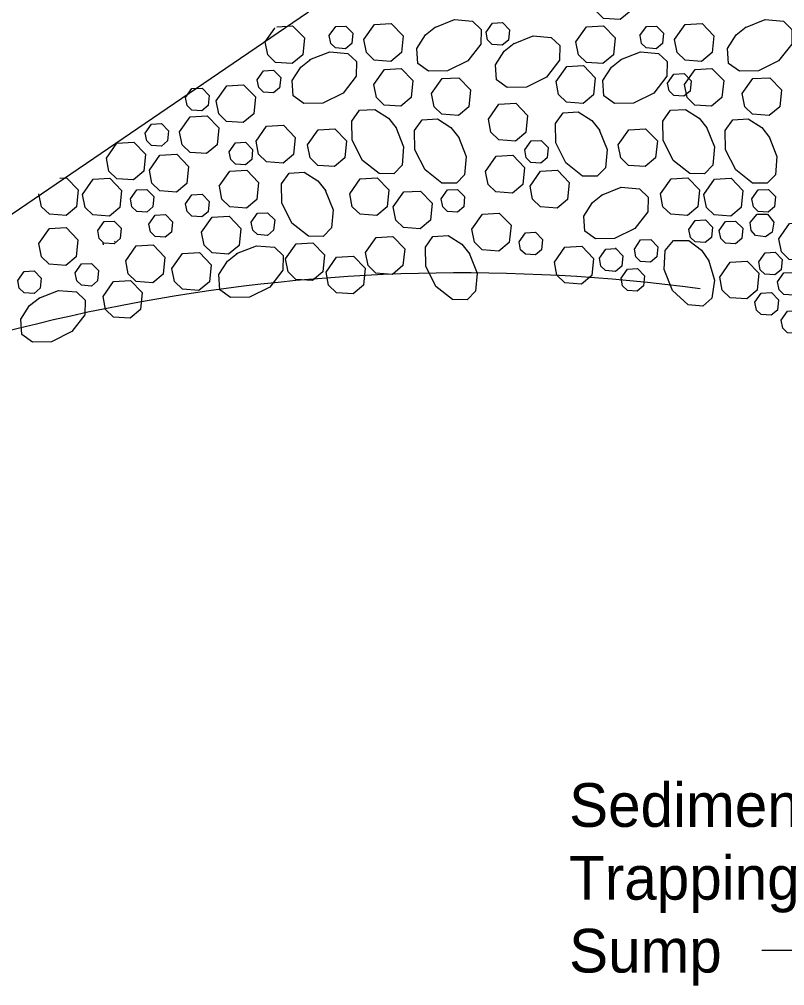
# Model space of a CAD drawing. Extents: x 6707406 to 6714471, y 1868570 to 1872341.
# Drawn here: x 6709570.8 to 6709696.9, y 1870139.3 to 1870298.5 of the extents above; entities that cross this region are included whole.
import ezdxf

# ---------------------------------------------------------------- set-up
doc = ezdxf.new("R2010")
doc.units = 0
for name, color, linetype in [('56 Stg 3 Anno', 7, 'Continuous'), ('57 Undefined', 7, 'Continuous'), ('60 Nongeo Data', 7, 'Continuous')]:
    doc.layers.add(name, color=color, linetype=linetype)

msp = doc.modelspace()

# ---------------------------------------------------------------- linework, layer by layer
at = {"layer": '56 Stg 3 Anno'}
msp.add_line((6709713.58, 1870145.05), (6709693.08, 1870145.05), dxfattribs=at)
at = {"layer": '60 Nongeo Data'}
msp.add_line((6709495.94, 1870216.26), (6709884.38, 1870481.01), dxfattribs=at)
for points in [[(6709665.33, 1870302.03), (6709667.07, 1870304.51), (6709669.85, 1870304.67), (6709671.78, 1870302.66), (6709671.5, 1870299.86), (6709669.79, 1870298.43), (6709667.04, 1870298.63), (6709665.75, 1870299.88), (6709665.34, 1870302.03)], [(6709639.21, 1870297.14), (6709642.47, 1870298.43), (6709645.46, 1870298.17), (6709646.88, 1870296.82), (6709646.83, 1870294.4), (6709644.68, 1870291.64), (6709641.34, 1870289.97), (6709638.2, 1870289.92), (6709636.44, 1870291.18), (6709636.27, 1870293.68), (6709637.7, 1870295.91), (6709639.35, 1870297.23)], [(6709690.41, 1870297.14), (6709693.66, 1870298.43), (6709696.65, 1870298.17), (6709698.07, 1870296.82), (6709698.03, 1870294.4), (6709695.87, 1870291.64), (6709692.54, 1870289.97), (6709689.4, 1870289.92), (6709687.63, 1870291.18), (6709687.46, 1870293.68), (6709688.9, 1870295.91), (6709690.54, 1870297.23)], [(6709613.19, 1870297.27), (6709615.8, 1870297.42), (6709617.74, 1870295.42), (6709617.46, 1870292.61), (6709615.74, 1870291.19), (6709613, 1870291.39), (6709611.71, 1870292.64), (6709611.29, 1870294.79)], [(6709611.29, 1870294.79), (6709612.88, 1870297.05)], [(6709612.88, 1870297.05), (6709612.88, 1870297.06)], [(6709621.84, 1870295.8), (6709622.89, 1870297.29), (6709624.55, 1870297.38), (6709625.71, 1870296.18), (6709625.54, 1870294.5), (6709624.51, 1870293.64), (6709622.87, 1870293.76), (6709622.09, 1870294.51), (6709621.84, 1870295.8)], [(6709627.54, 1870295.16), (6709629.28, 1870297.64), (6709632.06, 1870297.8), (6709633.99, 1870295.79), (6709633.71, 1870292.99), (6709631.99, 1870291.56), (6709629.25, 1870291.76), (6709627.96, 1870293.01), (6709627.54, 1870295.16)], [(6709647.67, 1870296.38), (6709648.71, 1870297.86), (6709650.38, 1870297.95), (6709651.54, 1870296.75), (6709651.37, 1870295.07), (6709650.34, 1870294.22), (6709648.7, 1870294.33), (6709647.92, 1870295.09), (6709647.67, 1870296.38)], [(6709662.48, 1870294.79), (6709664.22, 1870297.26), (6709667, 1870297.42), (6709668.93, 1870295.42), (6709668.65, 1870292.61), (6709666.93, 1870291.19), (6709664.19, 1870291.39), (6709662.9, 1870292.64), (6709662.48, 1870294.79)], [(6709673.03, 1870295.8), (6709674.08, 1870297.29), (6709675.74, 1870297.38), (6709676.9, 1870296.18), (6709676.74, 1870294.5), (6709675.71, 1870293.64), (6709674.06, 1870293.76), (6709673.29, 1870294.51), (6709673.04, 1870295.8)], [(6709678.74, 1870295.16), (6709680.47, 1870297.64), (6709683.25, 1870297.8), (6709685.18, 1870295.79), (6709684.9, 1870292.99), (6709683.19, 1870291.56), (6709680.45, 1870291.76), (6709679.15, 1870293.01), (6709678.74, 1870295.16)], [(6709652.18, 1870294.47), (6709655.43, 1870295.76), (6709658.42, 1870295.5), (6709659.84, 1870294.15), (6709659.79, 1870291.73), (6709657.64, 1870288.97), (6709654.31, 1870287.3), (6709651.17, 1870287.25), (6709649.4, 1870288.51), (6709649.23, 1870291.01), (6709650.67, 1870293.24), (6709652.31, 1870294.55)], [(6709618.66, 1870291.84), (6709621.91, 1870293.13), (6709624.9, 1870292.87), (6709626.32, 1870291.52), (6709626.28, 1870289.1), (6709624.12, 1870286.34), (6709620.79, 1870284.67), (6709617.65, 1870284.62), (6709615.88, 1870285.87), (6709615.71, 1870288.38), (6709617.15, 1870290.61), (6709618.79, 1870291.92)], [(6709669.85, 1870291.84), (6709673.11, 1870293.13), (6709676.1, 1870292.87), (6709677.52, 1870291.52), (6709677.47, 1870289.1), (6709675.32, 1870286.34), (6709671.98, 1870284.67), (6709668.84, 1870284.62), (6709667.08, 1870285.87), (6709666.91, 1870288.38), (6709668.34, 1870290.61), (6709669.99, 1870291.92)], [(6709629.18, 1870287.76), (6709630.92, 1870290.23), (6709633.69, 1870290.39), (6709635.62, 1870288.39), (6709635.35, 1870285.58), (6709633.63, 1870284.16), (6709630.89, 1870284.35), (6709629.6, 1870285.61), (6709629.18, 1870287.76)], [(6709659.21, 1870288.24), (6709660.95, 1870290.72), (6709663.73, 1870290.88), (6709665.66, 1870288.87), (6709665.38, 1870286.07), (6709663.66, 1870284.64), (6709660.92, 1870284.84), (6709659.63, 1870286.09), (6709659.21, 1870288.24)], [(6709680.37, 1870287.76), (6709682.11, 1870290.23), (6709684.89, 1870290.39), (6709686.82, 1870288.39), (6709686.54, 1870285.58), (6709684.82, 1870284.16), (6709682.08, 1870284.35), (6709680.79, 1870285.61), (6709680.37, 1870287.76)], [(6709609.96, 1870288.52), (6709611.01, 1870290.01), (6709612.67, 1870290.1), (6709613.83, 1870288.9), (6709613.66, 1870287.22), (6709612.63, 1870286.36), (6709610.99, 1870286.48), (6709610.21, 1870287.23), (6709609.96, 1870288.52)], [(6709638.69, 1870286.24), (6709640.43, 1870288.72), (6709643.2, 1870288.87), (6709645.13, 1870286.87), (6709644.85, 1870284.07), (6709643.14, 1870282.64), (6709640.4, 1870282.84), (6709639.11, 1870284.09), (6709638.69, 1870286.24)], [(6709677.58, 1870287.97), (6709678.62, 1870289.45), (6709680.29, 1870289.55), (6709681.45, 1870288.35), (6709681.28, 1870286.66), (6709680.25, 1870285.81), (6709678.61, 1870285.93), (6709677.83, 1870286.68), (6709677.58, 1870287.97)], [(6709689.88, 1870286.24), (6709691.62, 1870288.72), (6709694.4, 1870288.87), (6709696.33, 1870286.87), (6709696.05, 1870284.07), (6709694.33, 1870282.64), (6709691.59, 1870282.84), (6709690.3, 1870284.09), (6709689.88, 1870286.24)], [(6709598.16, 1870285.58), (6709599.2, 1870287.06), (6709600.87, 1870287.16), (6709602.03, 1870285.96), (6709601.86, 1870284.27), (6709600.83, 1870283.42), (6709599.18, 1870283.54), (6709598.41, 1870284.29), (6709598.16, 1870285.58)], [(6709603.21, 1870285.07), (6709604.95, 1870287.54), (6709607.73, 1870287.7), (6709609.66, 1870285.7), (6709609.38, 1870282.89), (6709607.67, 1870281.47), (6709604.92, 1870281.67), (6709603.63, 1870282.92), (6709603.22, 1870285.07)], [(6709648.05, 1870282.03), (6709649.79, 1870284.51), (6709652.57, 1870284.67), (6709654.5, 1870282.66), (6709654.22, 1870279.86), (6709652.51, 1870278.43), (6709649.77, 1870278.63), (6709648.48, 1870279.88), (6709648.06, 1870282.03)], [(6709597.18, 1870279.97), (6709598.92, 1870282.44), (6709601.7, 1870282.6), (6709603.63, 1870280.6), (6709603.35, 1870277.79), (6709601.63, 1870276.37), (6709598.89, 1870276.57), (6709597.6, 1870277.82), (6709597.18, 1870279.97)], [(6709632.8, 1870280.71), (6709634.09, 1870277.45), (6709633.83, 1870274.46), (6709632.48, 1870273.04), (6709630.05, 1870273.09), (6709627.3, 1870275.25), (6709625.63, 1870278.58), (6709625.58, 1870281.72), (6709626.83, 1870283.49), (6709629.33, 1870283.65), (6709631.57, 1870282.22), (6709632.88, 1870280.58)], [(6709666.31, 1870280.29), (6709667.6, 1870277.03), (6709667.35, 1870274.04), (6709666, 1870272.62), (6709663.57, 1870272.67), (6709660.81, 1870274.82), (6709659.15, 1870278.16), (6709659.09, 1870281.3), (6709660.35, 1870283.06), (6709662.85, 1870283.23), (6709665.09, 1870281.8), (6709666.4, 1870280.15)], [(6709683.99, 1870280.71), (6709685.28, 1870277.45), (6709685.02, 1870274.46), (6709683.67, 1870273.04), (6709681.25, 1870273.09), (6709678.49, 1870275.25), (6709676.83, 1870278.58), (6709676.77, 1870281.72), (6709678.03, 1870283.49), (6709680.53, 1870283.65), (6709682.76, 1870282.22), (6709684.07, 1870280.58)], [(6709591.5, 1870279.75), (6709592.54, 1870281.23), (6709594.21, 1870281.33), (6709595.37, 1870280.13), (6709595.2, 1870278.44), (6709594.17, 1870277.59), (6709592.53, 1870277.71), (6709591.75, 1870278.46), (6709591.5, 1870279.75)], [(6709609.77, 1870278.41), (6709611.51, 1870280.88), (6709614.29, 1870281.04), (6709616.22, 1870279.04), (6709615.94, 1870276.23), (6709614.22, 1870274.8), (6709611.48, 1870275), (6709610.19, 1870276.25), (6709609.77, 1870278.4)], [(6709643.11, 1870279.13), (6709644.4, 1870275.88), (6709644.14, 1870272.89), (6709642.79, 1870271.47), (6709640.37, 1870271.51), (6709637.61, 1870273.67), (6709635.94, 1870277), (6709635.89, 1870280.14), (6709637.14, 1870281.91), (6709639.65, 1870282.07), (6709641.88, 1870280.64), (6709643.19, 1870279)], [(6709694.3, 1870279.13), (6709695.59, 1870275.88), (6709695.34, 1870272.89), (6709693.98, 1870271.47), (6709691.56, 1870271.51), (6709688.8, 1870273.67), (6709687.14, 1870277), (6709687.08, 1870280.14), (6709688.34, 1870281.91), (6709690.84, 1870282.07), (6709693.08, 1870280.64), (6709694.39, 1870279)], [(6709618.24, 1870277.83), (6709619.98, 1870280.3), (6709622.76, 1870280.46), (6709624.69, 1870278.46), (6709624.41, 1870275.65), (6709622.7, 1870274.23), (6709619.96, 1870274.42), (6709618.67, 1870275.67), (6709618.25, 1870277.83)], [(6709669.44, 1870277.83), (6709671.18, 1870280.3), (6709673.95, 1870280.46), (6709675.89, 1870278.46), (6709675.61, 1870275.65), (6709673.89, 1870274.23), (6709671.15, 1870274.42), (6709669.86, 1870275.67), (6709669.44, 1870277.83)], [(6709585.11, 1870275.63), (6709586.85, 1870278.1), (6709589.62, 1870278.26), (6709591.56, 1870276.26), (6709591.28, 1870273.45), (6709589.56, 1870272.03), (6709586.82, 1870272.23), (6709585.53, 1870273.48), (6709585.11, 1870275.63)], [(6709605.35, 1870276.68), (6709606.39, 1870278.16), (6709608.06, 1870278.26), (6709609.21, 1870277.06), (6709609.05, 1870275.37), (6709608.02, 1870274.52), (6709606.37, 1870274.64), (6709605.6, 1870275.39), (6709605.35, 1870276.68)], [(6709654.03, 1870276.96), (6709655.08, 1870278.45), (6709656.74, 1870278.54), (6709657.9, 1870277.34), (6709657.73, 1870275.66), (6709656.7, 1870274.8), (6709655.06, 1870274.92), (6709654.28, 1870275.67), (6709654.03, 1870276.96)], [(6709592.19, 1870273.62), (6709593.93, 1870276.09), (6709596.7, 1870276.25), (6709598.63, 1870274.25), (6709598.35, 1870271.44), (6709596.64, 1870270.02), (6709593.9, 1870270.22), (6709592.61, 1870271.47), (6709592.19, 1870273.62)], [(6709647.57, 1870273.44), (6709649.31, 1870275.92), (6709652.08, 1870276.08), (6709654.01, 1870274.07), (6709653.74, 1870271.27), (6709652.02, 1870269.84), (6709649.28, 1870270.04), (6709647.99, 1870271.29), (6709647.57, 1870273.44)], [(6709603.72, 1870270.99), (6709605.46, 1870273.46), (6709608.24, 1870273.62), (6709610.17, 1870271.62), (6709609.89, 1870268.81), (6709608.18, 1870267.38), (6709605.43, 1870267.58), (6709604.14, 1870268.83), (6709603.73, 1870270.98)], [(6709621.17, 1870270.36), (6709622.46, 1870267.11), (6709622.2, 1870264.12), (6709620.85, 1870262.7), (6709618.43, 1870262.74), (6709615.67, 1870264.9), (6709614.01, 1870268.23), (6709613.95, 1870271.37), (6709615.21, 1870273.14), (6709617.71, 1870273.31), (6709619.94, 1870271.87), (6709621.25, 1870270.23)], [(6709654.92, 1870270.99), (6709656.66, 1870273.46), (6709659.43, 1870273.62), (6709661.37, 1870271.62), (6709661.09, 1870268.81), (6709659.37, 1870267.38), (6709656.63, 1870267.58), (6709655.34, 1870268.83), (6709654.92, 1870270.98)], [(6709577.42, 1870272.33), (6709578.53, 1870272.39), (6709580.46, 1870270.39), (6709580.18, 1870267.59), (6709578.46, 1870266.16), (6709575.72, 1870266.36), (6709574.43, 1870267.61), (6709574.01, 1870269.76)], [(6709581.17, 1870269.65), (6709582.91, 1870272.13), (6709585.68, 1870272.29), (6709587.62, 1870270.28), (6709587.34, 1870267.48), (6709585.62, 1870266.05), (6709582.88, 1870266.25), (6709581.59, 1870267.5), (6709581.17, 1870269.65)], [(6709625.21, 1870269.76), (6709626.94, 1870272.23), (6709629.72, 1870272.39), (6709631.65, 1870270.39), (6709631.37, 1870267.59), (6709629.66, 1870266.16), (6709626.92, 1870266.36), (6709625.63, 1870267.61), (6709625.21, 1870269.76)], [(6709676.4, 1870269.76), (6709678.14, 1870272.23), (6709680.92, 1870272.39), (6709682.85, 1870270.39), (6709682.57, 1870267.59), (6709680.85, 1870266.16), (6709678.11, 1870266.36), (6709676.82, 1870267.61), (6709676.4, 1870269.76)], [(6709683.55, 1870269.65), (6709685.29, 1870272.13), (6709688.07, 1870272.29), (6709690, 1870270.28), (6709689.72, 1870267.48), (6709688.01, 1870266.05), (6709685.26, 1870266.25), (6709683.97, 1870267.5), (6709683.56, 1870269.65)], [(6709589.08, 1870268.89), (6709590.12, 1870270.37), (6709591.79, 1870270.47), (6709592.95, 1870269.27), (6709592.78, 1870267.59), (6709591.75, 1870266.73), (6709590.11, 1870266.85), (6709589.33, 1870267.6), (6709589.08, 1870268.89)], [(6709598.16, 1870268.09), (6709599.2, 1870269.57), (6709600.87, 1870269.67), (6709602.03, 1870268.47), (6709601.86, 1870266.79), (6709600.83, 1870265.93), (6709599.18, 1870266.05), (6709598.41, 1870266.8), (6709598.16, 1870268.09)], [(6709632.36, 1870267.57), (6709634.1, 1870270.04), (6709636.88, 1870270.2), (6709638.81, 1870268.2), (6709638.53, 1870265.4), (6709636.81, 1870263.97), (6709634.07, 1870264.17), (6709632.78, 1870265.42), (6709632.36, 1870267.57)], [(6709640.28, 1870268.89), (6709641.32, 1870270.37), (6709642.99, 1870270.47), (6709644.14, 1870269.27), (6709643.98, 1870267.59), (6709642.95, 1870266.73), (6709641.3, 1870266.85), (6709640.53, 1870267.6), (6709640.28, 1870268.89)], [(6709666.7, 1870269.53), (6709669.95, 1870270.82), (6709672.94, 1870270.56), (6709674.36, 1870269.21), (6709674.32, 1870266.79), (6709672.16, 1870264.03), (6709668.83, 1870262.37), (6709665.69, 1870262.31), (6709663.92, 1870263.57), (6709663.75, 1870266.07), (6709665.19, 1870268.31), (6709666.83, 1870269.62)], [(6709691.47, 1870268.89), (6709692.51, 1870270.37), (6709694.18, 1870270.47), (6709695.34, 1870269.27), (6709695.17, 1870267.59), (6709694.14, 1870266.73), (6709692.49, 1870266.85), (6709691.72, 1870267.6), (6709691.47, 1870268.89)], [(6709608.97, 1870265.05), (6709610.02, 1870266.54), (6709611.68, 1870266.63), (6709612.84, 1870265.43), (6709612.67, 1870263.75), (6709611.64, 1870262.89), (6709610, 1870263.01), (6709609.22, 1870263.76), (6709608.97, 1870265.05)], [(6709645.33, 1870263.91), (6709647.07, 1870266.39), (6709649.85, 1870266.55), (6709651.78, 1870264.55), (6709651.5, 1870261.74), (6709649.78, 1870260.31), (6709647.04, 1870260.51), (6709645.75, 1870261.76), (6709645.33, 1870263.91)], [(6709583.7, 1870263.67), (6709584.74, 1870265.15), (6709586.41, 1870265.25), (6709587.57, 1870264.05), (6709587.4, 1870262.37), (6709586.37, 1870261.51), (6709584.72, 1870261.63), (6709583.95, 1870262.38), (6709583.7, 1870263.67)], [(6709592.13, 1870264.75), (6709593.17, 1870266.23), (6709594.84, 1870266.33), (6709595.99, 1870265.13), (6709595.83, 1870263.44), (6709594.8, 1870262.59), (6709593.15, 1870262.71), (6709592.38, 1870263.46), (6709592.13, 1870264.75)], [(6709600.81, 1870263.41), (6709602.55, 1870265.88), (6709605.32, 1870266.04), (6709607.26, 1870264.04), (6709606.98, 1870261.23), (6709605.26, 1870259.81), (6709602.52, 1870260.01), (6709601.23, 1870261.26), (6709600.81, 1870263.41)], [(6709681.09, 1870263.85), (6709682.13, 1870265.33), (6709683.8, 1870265.43), (6709684.96, 1870264.23), (6709684.79, 1870262.55), (6709683.76, 1870261.69), (6709682.11, 1870261.81), (6709681.34, 1870262.56), (6709681.09, 1870263.85)], [(6709686.08, 1870263.67), (6709687.13, 1870265.15), (6709688.79, 1870265.25), (6709689.95, 1870264.05), (6709689.79, 1870262.37), (6709688.76, 1870261.51), (6709687.11, 1870261.63), (6709686.34, 1870262.38), (6709686.09, 1870263.67)], [(6709691.2, 1870264.99), (6709692.36, 1870266.39), (6709694.03, 1870266.36), (6709695.09, 1870265.07), (6709694.79, 1870263.4), (6709693.7, 1870262.63), (6709692.07, 1870262.88), (6709691.35, 1870263.68), (6709691.2, 1870264.99)], [(6709695.9, 1870262.34), (6709697.64, 1870264.82), (6709700.41, 1870264.98), (6709702.34, 1870262.98), (6709702.06, 1870260.17), (6709700.35, 1870258.74), (6709697.61, 1870258.94), (6709696.32, 1870260.19), (6709695.9, 1870262.34)], [(6709573.98, 1870261.53), (6709575.72, 1870264), (6709578.49, 1870264.16), (6709580.42, 1870262.16), (6709580.14, 1870259.35), (6709578.43, 1870257.93), (6709575.69, 1870258.13), (6709574.4, 1870259.38), (6709573.98, 1870261.53)], [(6709653.12, 1870261.82), (6709654.16, 1870263.31), (6709655.83, 1870263.4), (6709656.99, 1870262.2), (6709656.82, 1870260.52), (6709655.79, 1870259.66), (6709654.14, 1870259.78), (6709653.37, 1870260.53), (6709653.12, 1870261.82)], [(6709586.44, 1870261.83), (6709586.57, 1870261.94)], [(6709627.81, 1870260.07), (6709629.55, 1870262.54), (6709632.33, 1870262.7), (6709634.26, 1870260.7), (6709633.98, 1870257.9), (6709632.26, 1870256.47), (6709629.52, 1870256.67), (6709628.23, 1870257.92), (6709627.81, 1870260.07)], [(6709644.89, 1870259.94), (6709646.18, 1870256.69), (6709645.92, 1870253.7), (6709644.57, 1870252.28), (6709642.14, 1870252.33), (6709639.39, 1870254.48), (6709637.72, 1870257.81), (6709637.67, 1870260.95), (6709638.92, 1870262.72), (6709641.42, 1870262.89), (6709643.66, 1870261.46), (6709644.97, 1870259.81)], [(6709672.1, 1870260.64), (6709673.14, 1870262.13), (6709674.81, 1870262.22), (6709675.97, 1870261.02), (6709675.8, 1870259.34), (6709674.77, 1870258.48), (6709673.13, 1870258.6), (6709672.35, 1870259.35), (6709672.1, 1870260.64)], [(6709684.3, 1870258.84), (6709685.33, 1870255.5), (6709684.84, 1870252.54), (6709683.39, 1870251.22), (6709680.97, 1870251.46), (6709678.39, 1870253.82), (6709676.99, 1870257.27), (6709677.18, 1870260.41), (6709678.57, 1870262.07), (6709681.07, 1870262.05), (6709683.19, 1870260.44), (6709684.37, 1870258.7)], [(6709584.66, 1870261.33), (6709584.61, 1870261.59)], [(6709588.3, 1870258.69), (6709590.04, 1870261.17), (6709592.82, 1870261.33), (6709594.75, 1870259.32), (6709594.47, 1870256.52), (6709592.75, 1870255.09), (6709590.01, 1870255.29), (6709588.72, 1870256.54), (6709588.3, 1870258.69)], [(6709606.56, 1870259.89), (6709609.82, 1870261.18), (6709612.81, 1870260.92), (6709614.23, 1870259.57), (6709614.18, 1870257.14), (6709612.03, 1870254.38), (6709608.69, 1870252.72), (6709605.55, 1870252.66), (6709603.79, 1870253.92), (6709603.62, 1870256.42), (6709605.05, 1870258.66), (6709606.7, 1870259.97)], [(6709614.63, 1870259.04), (6709616.36, 1870261.51), (6709619.14, 1870261.67), (6709621.07, 1870259.67), (6709620.79, 1870256.87), (6709619.08, 1870255.44), (6709616.34, 1870255.64), (6709615.05, 1870256.89), (6709614.63, 1870259.04)], [(6709658.93, 1870258.47), (6709660.67, 1870260.95), (6709663.45, 1870261.11), (6709665.38, 1870259.1), (6709665.1, 1870256.3), (6709663.38, 1870254.87), (6709660.64, 1870255.07), (6709659.35, 1870256.32), (6709658.93, 1870258.47)], [(6709666.34, 1870259.13), (6709667.39, 1870260.61), (6709669.05, 1870260.71), (6709670.21, 1870259.5), (6709670.05, 1870257.82), (6709669.02, 1870256.96), (6709667.37, 1870257.08), (6709666.6, 1870257.83), (6709666.35, 1870259.12)], [(6709669.05, 1870260.78), (6709669.04, 1870260.82)], [(6709692.6, 1870258.53), (6709693.64, 1870260.02), (6709695.31, 1870260.11), (6709696.47, 1870258.91), (6709696.3, 1870257.23), (6709695.27, 1870256.37), (6709693.62, 1870256.49), (6709692.85, 1870257.24), (6709692.6, 1870258.53)], [(6709595.92, 1870257.43), (6709597.66, 1870259.9), (6709600.44, 1870260.06), (6709602.37, 1870258.06), (6709602.09, 1870255.26), (6709600.37, 1870253.83), (6709597.63, 1870254.03), (6709596.34, 1870255.28), (6709595.92, 1870257.43)], [(6709621.31, 1870256.85), (6709623.05, 1870259.32), (6709625.82, 1870259.48), (6709627.75, 1870257.48), (6709627.47, 1870254.67), (6709625.76, 1870253.25), (6709623.02, 1870253.44), (6709621.73, 1870254.7), (6709621.31, 1870256.85)], [(6709686.17, 1870256.01), (6709687.91, 1870258.49), (6709690.68, 1870258.65), (6709692.62, 1870256.65), (6709692.34, 1870253.84), (6709690.62, 1870252.41), (6709687.88, 1870252.61), (6709686.59, 1870253.86), (6709686.17, 1870256.01)], [(6709570.52, 1870255.47), (6709571.56, 1870256.95), (6709573.23, 1870257.05), (6709574.38, 1870255.85), (6709574.22, 1870254.17), (6709573.19, 1870253.31), (6709571.54, 1870253.43), (6709570.77, 1870254.18), (6709570.52, 1870255.47)], [(6709579.97, 1870256.7), (6709581.01, 1870258.18), (6709582.68, 1870258.28), (6709583.84, 1870257.08), (6709583.67, 1870255.39), (6709582.64, 1870254.54), (6709581, 1870254.66), (6709580.22, 1870255.41), (6709579.97, 1870256.7)], [(6709669.92, 1870255.86), (6709670.96, 1870257.35), (6709672.63, 1870257.44), (6709673.79, 1870256.24), (6709673.62, 1870254.56), (6709672.59, 1870253.7), (6709670.95, 1870253.82), (6709670.17, 1870254.57), (6709669.92, 1870255.86)], [(6709584.57, 1870252.84), (6709586.3, 1870255.31), (6709589.08, 1870255.47), (6709591.01, 1870253.47), (6709590.73, 1870250.66), (6709589.02, 1870249.24), (6709586.28, 1870249.44), (6709584.99, 1870250.69), (6709584.57, 1870252.84)], [(6709695.71, 1870255.21), (6709696.75, 1870256.7), (6709698.42, 1870256.79), (6709699.58, 1870255.59), (6709699.41, 1870253.91), (6709698.38, 1870253.05), (6709696.73, 1870253.17), (6709695.96, 1870253.92), (6709695.71, 1870255.21)], [(6709573.96, 1870252.54), (6709577.22, 1870253.83), (6709580.21, 1870253.57), (6709581.63, 1870252.22), (6709581.58, 1870249.8), (6709579.43, 1870247.04), (6709576.09, 1870245.37), (6709572.95, 1870245.32), (6709571.18, 1870246.57), (6709571.02, 1870249.08), (6709572.45, 1870251.31), (6709574.09, 1870252.62)], [(6709691.96, 1870251.88), (6709693, 1870253.36), (6709694.67, 1870253.46), (6709695.83, 1870252.25), (6709695.66, 1870250.57), (6709694.63, 1870249.72), (6709692.99, 1870249.84), (6709692.21, 1870250.59), (6709691.96, 1870251.88)], [(6709696.3, 1870248.9), (6709697.34, 1870250.38), (6709699.01, 1870250.47), (6709700.17, 1870249.27), (6709700, 1870247.59), (6709698.97, 1870246.74), (6709697.32, 1870246.85), (6709696.55, 1870247.6), (6709696.3, 1870248.9)]]:
    msp.add_lwpolyline(points, dxfattribs=at)
msp.add_arc((6709643.67, 1869960.83), 295.87, 82.3714, 118.3095, dxfattribs=at)

# ---------------------------------------------------------------- texts
at = {"layer": '57 Undefined'}
for s, p in [('Sediment', (6709661.35, 1870165.45)), ('Trapping', (6709661.35, 1870153.45)), ('Sump', (6709661.35, 1870141.45))]:
    msp.add_text(s, height=7.2, dxfattribs=at).set_placement(p)

doc.saveas('drawing.dxf')
